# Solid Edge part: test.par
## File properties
Title: Thrust bearing
Author: Deepak Maini
Template: Normal.par
Last saved by: Robert a Rhodes jr
Revision: 8
Application: Solid Edge
Material: aluminum
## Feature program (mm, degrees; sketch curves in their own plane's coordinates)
sketch for "unnamed RevolvedProtrusion 1" plane through (0, 0, 0) normal (0, -1, 0) x-axis (1, 0, 0)
  line (47.625, 16.8036) -> (66.929, 16.8036)
  line (66.929, 16.8036) -> (73.025, 10.7076)
  line (73.025, 10.7076) -> (73.025, -12.0254)
  line (73.025, -12.0254) -> (66.929, -18.1214)
  line (66.929, -18.1214) -> (47.625, -18.1214)
  line (47.625, -18.1214) -> (47.625, -7.1994)
  line (61.5714, -7.1994) -> (47.625, -7.1994)
  line (61.5714, 5.8816) -> (61.5714, -7.1994)
  line (47.625, 5.8816) -> (61.5714, 5.8816)
  line (47.625, 5.8816) -> (47.625, 16.8036)
revolve "unnamed RevolvedProtrusion 1" add finite 360 deg
sketch for "unnamed RevolvedProtrusion 2" plane through (0, 0, 0) normal (1, 0, 0) x-axis (0, 1, 0)
  line (69.977, 13.7556) -> (73.0652, 13.7556)
  line (73.0652, 13.7556) -> (74.6125, 12.2083)
  line (74.6125, 12.2083) -> (74.6125, -13.4669)
  line (74.6125, -13.4669) -> (73.006, -15.0734)
  line (73.006, -15.0734) -> (69.977, -15.0734)
revolve "unnamed RevolvedProtrusion 2" add full turn 360 deg
sketch for "unnamed RevolvedProtrusion 3" plane through (0, 0, 0) normal (0, -1, 0) x-axis (1, 0, 0)
revolve "unnamed RevolvedProtrusion 3" add full turn 360 deg about sketch line (-54.9674, 10.1232) -> (-54.9674, -18.1214)
pattern "unnamed Pattern 1" of "unnamed RevolvedProtrusion 3"
pattern "unnamed Pattern 2"
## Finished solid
Body 1: solid body, 39 faces, 39 edges, 25 vertices.
  Faces by surface: torus 25, plane 6, cone 4, cylinder 4
  Edges by curve: circle 39
Bounding box of the edges (mm; curved faces can reach further): 149.225 x 149.225 x 34.925, from (-74.6125, -74.6125, -18.1214) to (74.6125, 74.6125, 16.8036).
Cylindrical faces by radius (mm): R47.625 x2, R61.5714 x1, R74.6125 x1
Conical faces (half-angle, radius in mm at the cone's reference point): 45 deg R66.929 x1, 45 deg R73.025 x1, 45 deg R73.0652 x1, 45 deg R74.6125 x1
Toroidal faces (ring radius, tube radius in mm): R-0.1023 r6.604 x25
Planar faces by outward normal: +z 3, -z 3
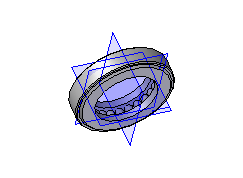
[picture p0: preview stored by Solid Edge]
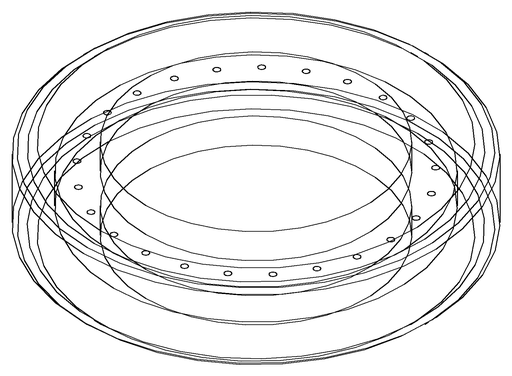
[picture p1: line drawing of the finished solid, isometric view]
